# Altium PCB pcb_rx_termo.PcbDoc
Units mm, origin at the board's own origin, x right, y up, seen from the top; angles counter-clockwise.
Board outline 53.97 x 58.8 mm, 2 copper layers (Top Layer, Bottom Layer); 23 components, 38 nets, 138 pads, 17 vias.
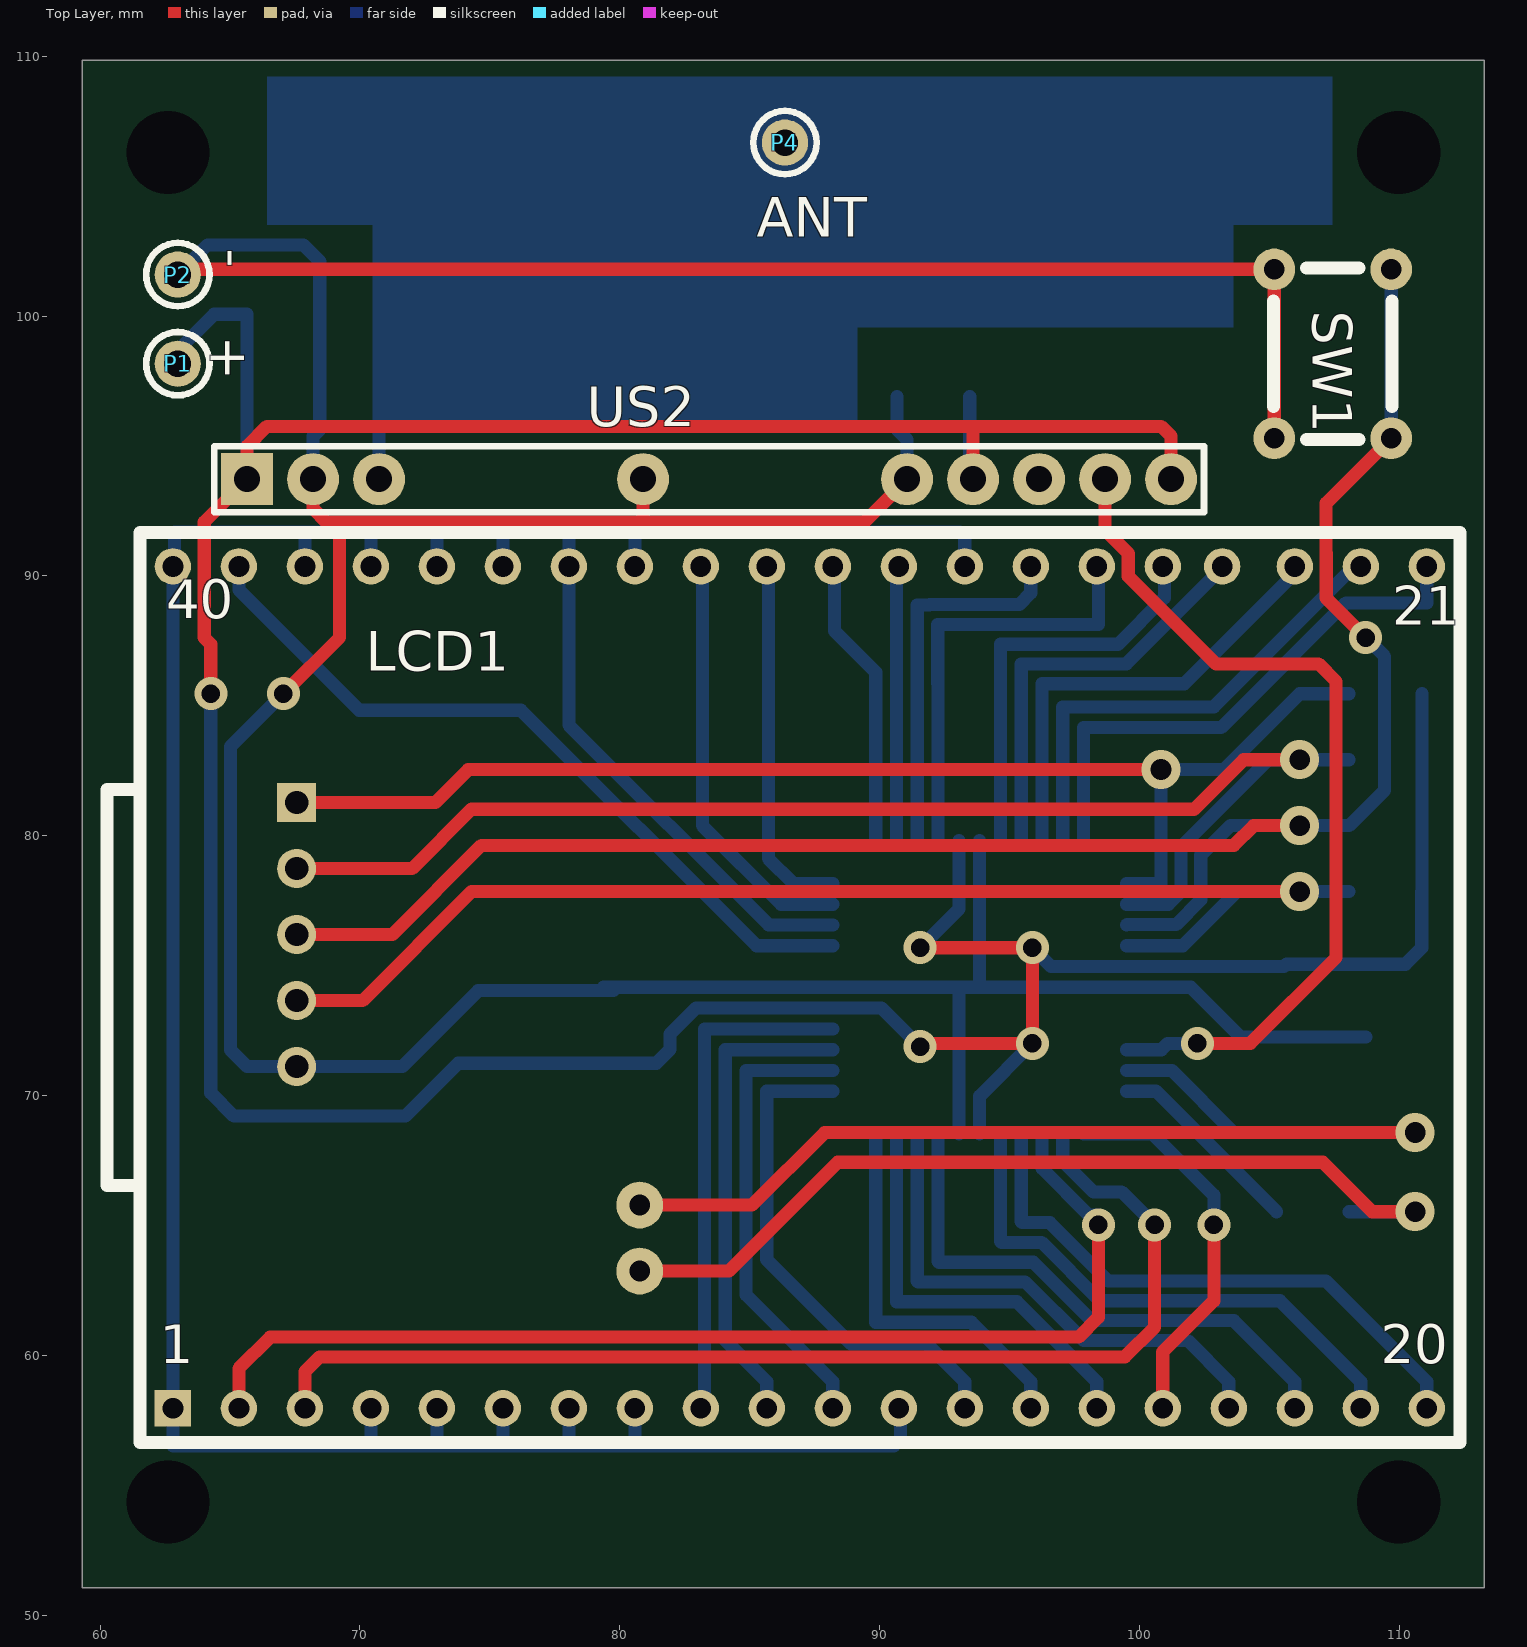
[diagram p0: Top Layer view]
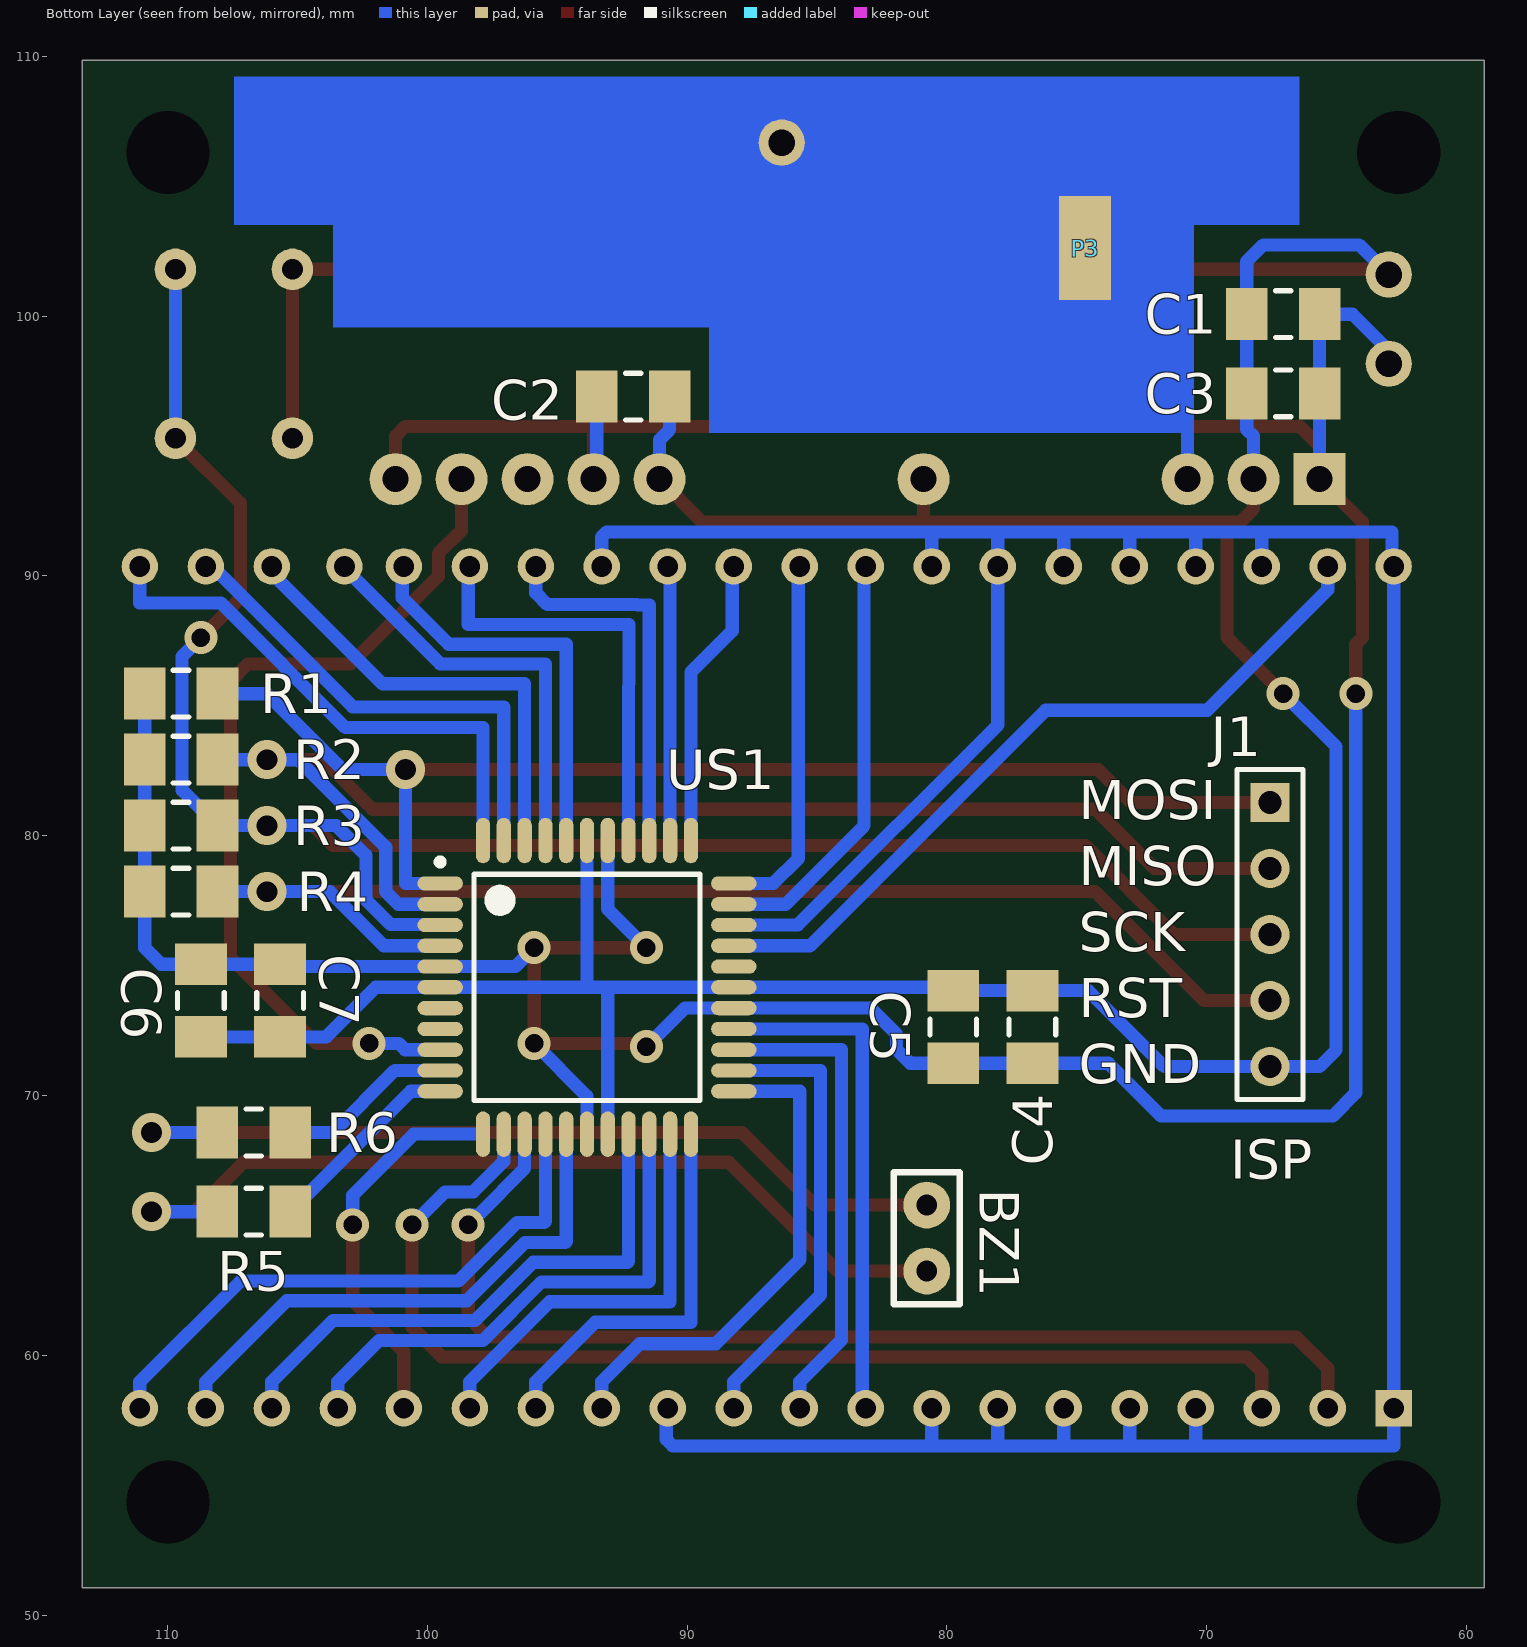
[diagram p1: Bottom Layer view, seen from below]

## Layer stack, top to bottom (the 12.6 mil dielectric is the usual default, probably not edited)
Top Layer: signal copper 0.0356
Dielectric: dielectric 0.32, FR-4, Dk 4.8
Bottom Layer: signal copper 0.0356

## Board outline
59.309,51.054 59.309,109.855 113.284,109.855 113.284,51.054

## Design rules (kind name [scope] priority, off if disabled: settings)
Clearance [All] p1: gap=0.254
PolygonConnect [All] p1: connectstyle=Relief reliefconductorwidth=0.254 reliefentries=4 polygonreliefangle="90 Angle"
RoutingVias [All] p1: holewidth=0.711 width=1.27 viastyle="Through Hole" minholewidth=0.711 minwidth=1.27 maxholewidth=0.711 maxwidth=1.27
SilkscreenOverComponentPads [All] p1: minsilkscreentomaskgap=0.254
SolderMaskExpansion [All] p1: expansion=0.102
Width [All] p1: maxlimit=2.54 minlimit=0.254 preferedwidth=0.508
27 further rules are at their usual default settings.

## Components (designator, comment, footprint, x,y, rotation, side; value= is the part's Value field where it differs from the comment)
BZ1 "piezo 20mm" "buzzer piezo - tylko piny" 80.772,64.516 r270 bottom
C1 "1u" MELF-1206 67.056,100.076 r180 bottom
C2 "10n" MELF-1206 92.075,96.901 r0 bottom
C3 "10n" MELF-1206 67.056,97.028 r180 bottom
C4 "100n" MELF-1206 76.708,72.644 r270 bottom
C5 "10n" MELF-1206 79.756,72.644 r270 bottom
C6 "1u" MELF-1206 108.712,73.66 r90 bottom
C7 "10n" MELF-1206 105.664,73.66 r90 bottom
J1 "Goldpin 5pin" HDR1X5 67.564,81.28 r270 bottom
LCD1 "JH17" "LCD JH17" 88.203,74.168 r0 top
P1 "Pad" "pad fi 1mm" 62.992,98.171 r180 top
P2 "Pad" "pad fi 1mm" 62.992,101.6 r180 top
P3 "ANT" "Pad SMD 2x4mm" 74.676,102.616 r90 bottom
P4 "ANT" "pad fi 1mm" 86.36,106.68 r0 top
R1 "10k" MELF-1206 109.474,85.471 r180 bottom
R2 "10k" MELF-1206 109.474,82.931 r180 bottom
R3 "10k" MELF-1206 109.474,80.391 r180 bottom
R4 "10k" MELF-1206 109.474,77.851 r180 bottom
R5 "36" MELF-1206 106.68,65.532 r0 bottom
R6 "36" MELF-1206 106.68,68.58 r0 bottom
SW1 "switch 6x6" "tact switch 6x6" 107.442,98.552 r90 top
US1 "ATmega16L" 44A_N 93.853,74.168 r180 bottom
US2 "ZS-RR8-433" RR8_Rx 65.659,93.726 r0 top

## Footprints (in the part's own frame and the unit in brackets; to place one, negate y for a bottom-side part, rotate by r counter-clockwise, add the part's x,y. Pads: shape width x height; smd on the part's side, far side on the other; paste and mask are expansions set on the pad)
44A_N [mm] "Thin QFP, 44-Leads, Body 10x10mm, Pitch 0.8mm, IPC Medium Density"
  oval 1.75x0.55 smd: 1(-5.65,4) 2(-5.65,3.2) 3(-5.65,2.4) 4(-5.65,1.6) 5(-5.65,0.8) 6(-5.65,0) 7(-5.65,-0.8) 8(-5.65,-1.6) 9(-5.65,-2.4) 10(-5.65,-3.2) 11(-5.65,-4) 23(5.65,-4) 24(5.65,-3.2) 25(5.65,-2.4) 26(5.65,-1.6) 27(5.65,-0.8) 28(5.65,0) 29(5.65,0.8) 30(5.65,1.6) 31(5.65,2.4) 32(5.65,3.2) 33(5.65,4)
  oval 0.55x1.75 smd: 12(-4,-5.65) 13(-3.2,-5.65) 14(-2.4,-5.65) 15(-1.6,-5.65) 16(-0.8,-5.65) 17(0,-5.65) 18(0.8,-5.65) 19(1.6,-5.65) 20(2.4,-5.65) 21(3.2,-5.65) 22(4,-5.65) 34(4,5.65) 35(3.2,5.65) 36(2.4,5.65) 37(1.6,5.65) 38(0.8,5.65) 39(0,5.65) 40(-0.8,5.65) 41(-1.6,5.65) 42(-2.4,5.65) 43(-3.2,5.65) 44(-4,5.65)
  silkscreen extent -5.77,-4.35 4.35,4.95, body extent -5,-5 5,5, height 1.2
"buzzer piezo - tylko piny" [mm]
  round 1.8 hole 0.8: 1(-1.27,0) 2(1.27,0)
  silkscreen extent -2.54,-1.27 2.54,1.27
HDR1X5 [mm] "Connector; Header; 5 Position"
  rect 1.5x1.5 hole 0.9: 1(0,0)
  round 1.5 hole 0.9: 2(2.54,0) 3(5.08,0) 4(7.62,0) 5(10.16,0)
  silkscreen extent -1.27,-1.27 11.43,1.27
"LCD JH17" [mm]
  rect 1.4x1.4 hole 0.8: 1(-25.4,-16.2)
  round 1.4 hole 0.8: 2(-22.86,-16.2) 3(-20.32,-16.2) 4(-17.78,-16.2) 5(-15.24,-16.2) 6(-12.7,-16.2) 7(-10.16,-16.2) 8(-7.62,-16.2) 9(-5.08,-16.2) 10(-2.54,-16.2) 11(0,-16.2) 12(2.54,-16.2) 13(5.08,-16.2) 14(7.62,-16.2) 15(10.16,-16.2) 16(12.7,-16.2) 17(15.24,-16.2) 18(17.78,-16.2) 19(20.32,-16.2) 20(22.86,-16.2) 21(22.86,16.2) 22(20.32,16.2) 23(17.78,16.2) 24(14.986,16.2) 25(12.7,16.2) 26(10.16,16.2) 27(7.62,16.2) 28(5.08,16.2) 29(2.54,16.2) 30(0,16.2) 31(-2.54,16.2) 32(-5.08,16.2) 33(-7.62,16.2) 34(-10.16,16.2) 35(-12.7,16.2) 36(-15.24,16.2) 37(-17.78,16.2) 38(-20.32,16.2) 39(-22.86,16.2) 40(-25.4,16.2)
  silkscreen extent -27.94,-17.51 24.13,17.51
MELF-1206 [mm] "Metal Electrode Face (MELF) Resistor; Body 3.2 x 1.8 mm (LxDia)"
  rect 1.6x2 smd: 1(-1.4,0) 2(1.4,0)
  silkscreen extent -0.3,-0.9 0.3,0.9, body extent -2.3,-1.1 2.3,1.1, height 1.85
"pad fi 1mm" [mil]
  round 70 hole 40: 1(0,0)
  silkscreen extent -48,-48 48,48
"Pad SMD 2x4mm" [mm]
  rect 4x2 smd: 1(0,0)
RR8_Rx [mm]
  rect 2x2 hole 1: 1(0,0)
  round 2 hole 1: 2(2.54,0) 3(5.08,0) 7(15.24,0) 11(25.4,0) 12(27.94,0) 13(30.48,0) 14(33.02,0) 15(35.56,0)
  silkscreen extent -1.27,-1.27 36.83,1.27
"tact switch 6x6" [mm]
  round 1.6 hole 0.8: 1(3.25,2.25) 2(3.25,-2.25) 3(-3.25,2.25) 4(-3.25,-2.25)
  silkscreen extent -3.3,-2.29 3.3,2.29

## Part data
BZ1: library part "buzzer piezo"
C1 C2 C3 C4 C5 C6 C7: library part kondensator
J1: library part "Header 5", "Header, 5-Pin"
LCD1: library part "LCD JH17"
P3: library part Pad, "Pad"
P4: library part Pad
R1 R2 R3 R4 R5 R6: library part rezystor
SW1: library part switch
US1: library part ATmega32-16AC, "8-Bit AVR Microcontroller with 32K Bytes of In-System Programmable Flash Memory"
US2: library part RR8_Rx

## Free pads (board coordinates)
  round 0 hole 3.2: 0(62.611,54.356) 1(62.611,106.299) 2(109.982,54.356) 3(109.982,106.299)

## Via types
v1: diameter 1.27, hole 0.711, Top Layer to Bottom Layer, 11 vias
v2: diameter 1.5, hole 0.8, Top Layer to Bottom Layer, 6 vias

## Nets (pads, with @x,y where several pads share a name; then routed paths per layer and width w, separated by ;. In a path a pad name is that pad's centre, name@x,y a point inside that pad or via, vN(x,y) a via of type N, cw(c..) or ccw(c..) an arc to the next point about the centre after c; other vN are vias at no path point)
1A: LCD1.30 US1.34 | length 11.1
  Bottom Layer w0.508: LCD1.30@88.265,90.306 88.265,87.884 89.853,86.296 US1.34
1B: LCD1.29 US1.35 | length 10.5
  Bottom Layer w0.508: US1.35 90.653,89.256 LCD1.29@90.653,90.278
1C: LCD1.11 US1.24 | length 17.7
  Bottom Layer w0.508: LCD1.11 88.203,58.99 84.861,62.332 84.861,70.968 US1.24
1D: LCD1.10 US1.25 | length 18.6
  Bottom Layer w0.508: LCD1.10 85.663,58.99 84.061,60.592 84.061,71.768 US1.25
1E: LCD1.9 US1.26 | length 19.5
  Bottom Layer w0.508: LCD1.9@83.261,57.968 83.261,72.568 US1.26
1F: LCD1.31 US1.33 | length 14.1
  Bottom Layer w0.508: LCD1.31@85.725,90.306 85.725,86.17 85.725,79.121 86.678,78.168 US1.33
1G: LCD1.32 US1.32 | length 16.2
  Bottom Layer w0.508: LCD1.32@83.185,90.306 83.185,86.97 83.185,80.391 86.208,77.368 US1.32
2A: LCD1.25 US1.40 | length 15.8
  Bottom Layer w0.508: US1.40 94.653,87.376 95.137,87.376 99.181,87.376 100.965,89.16 LCD1.25@100.965,90.368
2B: LCD1.24 US1.41 | length 16.1
  Bottom Layer w0.508: US1.41 95.453,86.614 99.497,86.614 LCD1.24@103.251,90.368
2C: LCD1.15 US1.21 | length 16.5
  Bottom Layer w0.508: US1.21 90.653,62.065 95.288,62.065 98.363,58.99 LCD1.15
2D: LCD1.14 US1.22 | length 15.2
  Bottom Layer w0.508: US1.22 89.853,61.278 93.535,61.278 95.823,58.99 LCD1.14
2E: LCD1.13 US1.23 | length 19.6
  Bottom Layer w0.508: US1.23 85.661,70.168 85.661,63.691 88.9,60.452 91.821,60.452 93.283,58.99 LCD1.13
2F: LCD1.26 US1.37 | length 16.7
  Bottom Layer w0.508: US1.37 92.253,84.709 92.24,86.868 92.24,88.138 98.425,88.138 LCD1.26@98.425,90.368
2G: LCD1.27 US1.36 | length 14.7
  Bottom Layer w0.508: US1.36 91.453,88.887 91.912,88.887 91.925,88.9 93.931,88.9 95.377,88.9 95.823,89.346 LCD1.27
3A: LCD1.21 US1.44 | length 20.9
  Bottom Layer w0.508: US1.44 97.853,84.163 103.148,84.163 107.95,88.965 111.063,88.965 LCD1.21
3B: LCD1.20 US1.15 | length 22.6
  Bottom Layer w0.508: US1.15 95.453,65.151 95.491,65.113 96.551,65.113 98.799,62.865 104.263,62.865 107.188,62.865 111.063,58.99 LCD1.20
3C: LCD1.19 US1.16 | length 21.3
  Bottom Layer w0.508: US1.16 94.653,64.389 94.691,64.351 96.235,64.351 98.483,62.103 103.948,62.103 105.41,62.103 108.523,58.99 LCD1.19
3D: LCD1.18 US1.19 | length 21.6
  Bottom Layer w0.508: US1.19 92.253,63.627 92.291,63.589 95.919,63.589 98.167,61.341 103.632,61.341 105.983,58.99 LCD1.18
3E: LCD1.17 US1.20 | length 20.3
  Bottom Layer w0.508: US1.20 91.453,62.865 91.491,62.827 95.604,62.827 97.852,60.579 101.854,60.579 103.443,58.99 LCD1.17
3F: LCD1.22 US1.43 | length 18.9
  Bottom Layer w0.508: US1.43 97.053,84.963 102.87,84.963 108.275,90.368 LCD1.22
3G: LCD1.23 US1.42 | length 17.8
  Bottom Layer w0.508: US1.42 96.253,85.852 101.727,85.852 105.983,90.108 LCD1.23
BUZ1: R5.1 US1.11 | length 7.7
  Bottom Layer w0.508: US1.11 100.644,70.168 R5.1
BUZ2: R6.1 US1.10 | length 6.8
  Bottom Layer w0.508: US1.10 101.244,70.968 103.632,68.58 R6.1
COM: LCD1.1 LCD1.4 LCD1.5 LCD1.6 LCD1.7 LCD1.8 LCD1.12 LCD1.28 LCD1.33 LCD1.34 LCD1.35 LCD1.36 LCD1.37 LCD1.38 LCD1.40 US1.31 | length 130.6
  Bottom Layer w0.508: LCD1.38 67.883,91.629 67.818,91.694 ; 70.423,56.515 LCD1.4 ; LCD1.37 70.423,91.632 ; 72.963,56.515 LCD1.5 ; LCD1.36 72.963,91.632 ; 75.503,56.515 LCD1.6 ; LCD1.35 75.503,91.632 ; 78.043,56.515 LCD1.7 ; 78.043,91.629 LCD1.34 78.043,87.314 78.043,84.263 85.738,76.568 US1.31 ; 80.583,56.515 LCD1.8 ; LCD1.33 80.583,91.629 ; LCD1.12 90.805,57.906 90.805,56.769 90.551,56.515 62.803,56.515 LCD1.1 LCD1.40 62.865,90.43 62.865,91.694 67.818,91.694 ; LCD1.28 93.283,91.502 93.091,91.694 67.818,91.694
GND: C1.1 C2.1 C3.1 C4.1 C5.1 C6.1 C7.1 J1.5 P2.1 SW1.1 SW1.3 US1.6 US1.18 US1.28 US1.39 US2.2 US2.7 US2.11 | length 172.9
  Top Layer w0.508: P2.1 63.194,101.802 SW1.1 SW1.3 ; v1(67.056,85.471) 69.215,87.63 69.215,92.075 ; US2.2 68.199,92.583 68.707,92.075 69.215,92.075 ; US2.7 80.899,92.075 ; US2.11 89.408,92.075 80.899,92.075 ; 69.215,92.075 80.899,92.075
  Bottom Layer w0.508: P2.1 64.135,102.743 67.818,102.743 68.456,102.105 C1.1 C3.1 68.456,95.634 68.199,95.377 US2.2 ; v1(67.056,85.471) 65.024,83.439 65.024,71.755 65.659,71.12 J1.5 71.628,71.12 74.552,74.044 C4.1 C5.1 ; C5.1@79.372,74.168 US1.28 93.853,74.168 ; C2.1 90.675,95.634 91.059,95.25 US2.11 ; US1.18 93.053,74.003 ; US1.39 93.853,74.168 ; C6.1 C7.1 103.889,72.26 101.981,74.168 US1.6 93.853,74.168
K: LCD1.3 US1.13 | length 44.3
  Top Layer w0.508: LCD1.3 67.883,59.374 68.453,59.944 99.441,59.944 100.584,61.087 v1(100.584,65.024)
  Bottom Layer w0.508: US1.13 97.053,67.474 98.233,66.294 99.314,66.294 v1(100.584,65.024)
MISO: J1.2 R2.2 US1.2 | length 52.2
  Top Layer w0.508: J1.2 72.009,78.74 74.295,81.026 102.108,81.026 104.013,82.931 v2(106.172,82.931)
  Bottom Layer w0.508: US1.2 101.117,77.368 101.6,77.851 101.6,79.564 104.967,82.931 v2(106.172,82.931) R2.2
MOSI: J1.1 R1.2 US1.1 | length 48
  Top Layer w0.508: J1.1 72.898,81.28 74.168,82.55 v2(100.838,82.55)
  Bottom Layer w0.508: US1.1 100.837,78.168 100.838,78.169 v2(100.838,82.55) 103.251,82.55 106.172,85.471 R1.2
NetBZ1_1: BZ1.1 R6.2 | length 33.5
  Top Layer w0.508: BZ1.1 85.09,65.786 87.884,68.58 v2(110.617,68.58)
  Bottom Layer w0.508: R6.2 v2(110.617,68.58)
NetBZ1_2: BZ1.2 R5.2 | length 34.9
  Top Layer w0.508: BZ1.2 84.201,63.246 88.392,67.437 107.061,67.437 108.966,65.532 v2(110.617,65.532)
  Bottom Layer w0.508: R5.2 v2(110.617,65.532)
NetP3_1: P3.1 P4.1 US2.3 | length 25.2
  Bottom Layer w0.508: US2.3 70.739,100.965 72.39,102.616 P3.1 ; P3.1@74.676,102.743 77.216,102.743 81.153,106.68 P4.1
OUT: US1.9 US2.14 | length 33.9
  Top Layer w0.508: US2.14 98.679,91.76 99.571,90.868 99.571,89.992 102.949,86.614 106.899,86.614 107.569,85.944 107.569,75.311 104.267,72.009 v1(102.235,72.009)
  Bottom Layer w0.508: US1.9 100.851,71.768 101.092,72.009 v1(102.235,72.009)
P3: LCD1.16 US1.12 | length 15
  Top Layer w0.508: LCD1.16 100.903,60.136 102.87,62.103 v1(102.87,65.024)
  Bottom Layer w0.508: US1.12 100.519,68.518 102.87,66.167 v1(102.87,65.024)
RESET: J1.4 R4.2 US1.4 | length 49.8
  Top Layer w0.508: J1.4 70.104,73.66 74.295,77.851 v2(106.172,77.851)
  Bottom Layer w0.508: US1.4 101.672,75.768 103.755,77.851 v2(106.172,77.851) R4.2
SCK: J1.3 R3.2 SW1.2 SW1.4 US1.3 | length 75.5
  Top Layer w0.508: J1.3 71.247,76.2 74.676,79.629 103.632,79.629 104.394,80.391 v2(106.172,80.391) ; v1(108.712,87.63) 107.191,89.151 107.191,90.871 107.188,90.874 107.188,92.798 SW1.4 SW1.4@109.731,95.263
  Bottom Layer w0.508: US1.3 99.52,76.585 101.412,76.585 102.362,77.535 102.362,79.248 103.505,80.391 v2(106.172,80.391) R3.2 109.439,81.756 109.439,86.903 v1(108.712,87.63) ; SW1.4 SW1.2
VCC: C1.2 C2.2 C3.2 C4.2 C5.2 C6.2 C7.2 P1.1 R1.1 R2.1 R3.1 R4.1 US1.5 US1.17 US1.27 US1.38 US2.1 US2.12 US2.15 | length 156.3
  Top Layer w0.508: v1(64.262,85.471) 64.262,87.376 64.008,87.63 64.008,89.862 64.011,89.865 64.011,92.078 US2.1 65.659,94.996 66.421,95.758 93.599,95.758 ; v1(91.567,71.882) 91.694,72.009 v1(95.885,72.009) v1(95.885,75.692) v1(91.567,75.692) ; US2.12 93.599,95.758 ; US2.15 101.219,95.377 100.838,95.758 93.599,95.758
  Bottom Layer w0.508: P1.1 62.992,98.679 64.389,100.076 C1.2 C3.2 ; v1(64.262,85.471) 64.262,70.104 65.151,69.215 71.755,69.215 73.784,71.244 C4.2 C5.2 ; US2.1 C3.2@65.659,97.025 ; C5.2@79.248,71.244 C5.2 ; v1(91.567,71.882) 90.081,73.368 US1.27 82.931,73.368 81.934,72.371 81.934,71.771 81.407,71.244 C5.2 ; v1(91.567,75.692) 93.053,77.178 US1.38 ; C2.2 93.475,93.85 US2.12 ; US1.17 93.853,69.977 v1(95.885,72.009) ; v1(95.885,75.692) 96.609,74.968 US1.5 C7.2@105.572,74.968 ; C7.2 110.239,75.06 110.871,75.692 110.871,77.848 R4.1 R3.1 R2.1 R1.1
X: LCD1.39 US1.30 | length 29.4
  Bottom Layer w0.508: LCD1.39 65.343,89.47 69.977,84.836 76.2,84.836 85.268,75.768 US1.30
Y: LCD1.2 US1.14 | length 43.6
  Top Layer w0.508: LCD1.2 65.343,59.501 66.548,60.706 97.663,60.706 98.425,61.468 v1(98.425,65.024)
  Bottom Layer w0.508: US1.14 96.253,67.196 98.044,65.405 98.425,65.405 v1(98.425,65.024)
pads on no net: US1.7 US1.8 US1.29 US2.13

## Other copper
Bottom Layer:
  rectangle net NetP3_1: 66.421,103.505 70.612,109.22
  rectangle net NetP3_1: 70.485,99.568 103.632,109.22
  rectangle net NetP3_1: 70.739,95.504 89.154,100.965
  rectangle net NetP3_1: 103.251,103.505 107.442,109.22

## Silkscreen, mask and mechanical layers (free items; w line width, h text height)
Top Overlay:
  text "+    -" at 66.04,97.536 h2.54 r90
Bottom Overlay:
  text "MOSI" at 74.93,80.645 h1.5
  text "MISO" at 74.93,78.105 h1.5
  text "SCK" at 74.93,75.565 h1.5
  text "RST" at 74.93,73.025 h1.5
  text "GND" at 74.93,70.485 h1.5
  text "ISP" at 69.088,66.802 h1.5
Mechanical 1:
  the board outline again, w0.5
